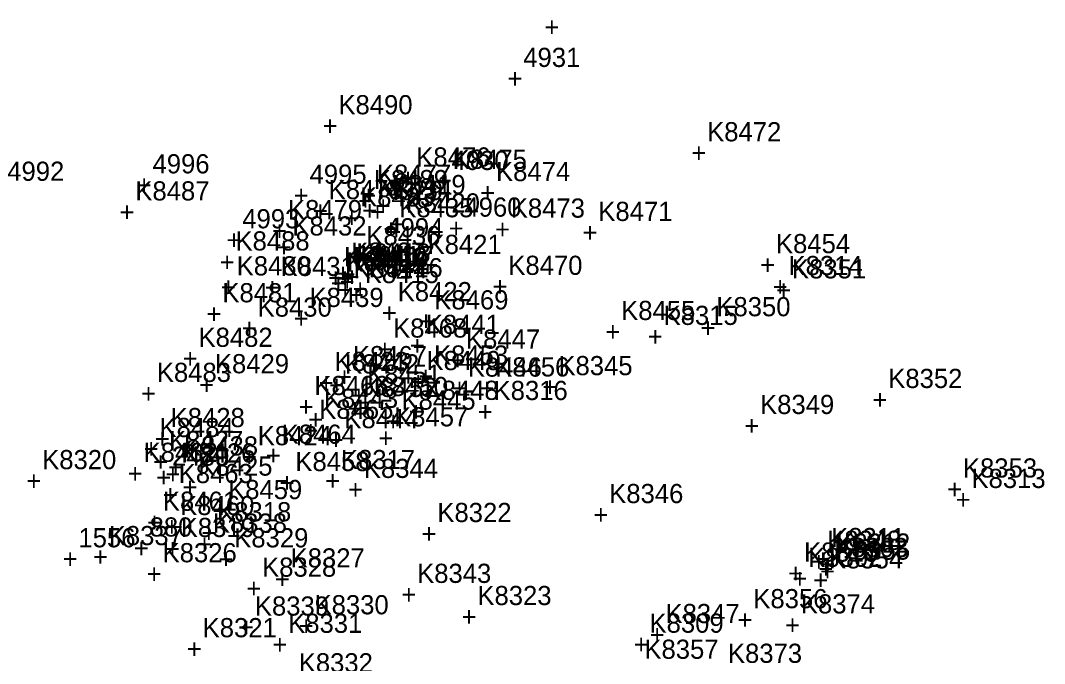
# Model space of a CAD drawing. Extents: x 1036751 to 1042192, y 772604 to 785439.
# Drawn here: x 1038800.5 to 1038934, y 778110.9 to 778194.7 of the extents above; entities that cross this region are included whole.
import ezdxf

# ---------------------------------------------------------------- set-up
doc = ezdxf.new("R2010")
doc.units = 0
for name, color, linetype in [('S_Control_Temp_Traverse', 7, 'Continuous'), ('S_Curb_Type_3', 7, 'Continuous'), ('S_Drainage_Culvert_Top', 7, 'Continuous'), ('S_Drainage_Ditch_Line', 7, 'Continuous'), ('S_Drainage_Invert', 7, 'Continuous'), ('S_Drainage_RipRap', 7, 'Continuous'), ('S_Ground_Elevation', 7, 'Continuous'), ('S_Ground_LevelString', 7, 'Continuous'), ('S_Misc_MiscItems', 7, 'Continuous'), ('S_Property_Garden', 7, 'Continuous'), ('S_Roadway_Drive_Paved', 7, 'Continuous'), ('S_Roadway_Edge_Pavement', 7, 'Continuous'), ('S_Roadway_Painted_Lines', 7, 'Continuous'), ('S_Traffic_JunctionBox', 7, 'Continuous'), ('S_Traffic_Sign_Base', 7, 'Continuous'), ('S_Traffic_Sign_SinglePost', 7, 'Continuous'), ('S_Trees_TreeLine', 7, 'Continuous')]:
    doc.layers.add(name, color=color, linetype=linetype)

msp = doc.modelspace()

# ---------------------------------------------------------------- texts
at = {"layer": 'S_Control_Temp_Traverse'}
for s, p in [('880', (1038817.35, 778127.4)), ('880', (1038817.35, 778127.4)), ('+', (1038815.29, 778124.65)), ('+', (1038815.29, 778124.65))]:
    msp.add_text(s, height=2.5, dxfattribs=at).set_placement(p)
at = {"layer": 'S_Curb_Type_3'}
for s, p in [('K8303', (1038906.58, 778124.72)), ('K8302', (1038903.21, 778123.45)), ('+', (1038904.52, 778121.97)), ('+', (1038901.14, 778120.7))]:
    msp.add_text(s, height=2.5, dxfattribs=at).set_placement(p)
at = {"layer": 'S_Drainage_Culvert_Top'}
for s, p in [('K8411', (1038844.18, 778162.13)), ('+', (1038842.12, 778159.38)), ('2479', (1038820.26, 778136.62)), ('+', (1038818.2, 778133.87))]:
    msp.add_text(s, height=2.5, dxfattribs=at).set_placement(p)
at = {"layer": 'S_Drainage_Ditch_Line'}
for s, p in [('K8440', (1038842.69, 778162.63)), ('+', (1038840.63, 778159.88)), ('K8439', (1038838.19, 778157.32)), ('+', (1038836.13, 778154.57)), ('K8438', (1038821.82, 778137.96)), ('+', (1038819.76, 778135.21))]:
    msp.add_text(s, height=2.5, dxfattribs=at).set_placement(p)
at = {"layer": 'S_Drainage_Invert'}
for s, p in [('K8410', (1038843.93, 778162.53)), ('+', (1038841.87, 778159.78)), ('2480', (1038820.29, 778136.64)), ('+', (1038818.23, 778133.89))]:
    msp.add_text(s, height=2.5, dxfattribs=at).set_placement(p)
at = {"layer": 'S_Drainage_RipRap'}
for s, p in [('K8419', (1038848.88, 778172.02)), ('K8433', (1038844.79, 778170.42)), ('K8434', (1038847.12, 778171.41)), ('K8420', (1038850.74, 778169.63)), ('+', (1038845.06, 778168.66)), ('+', (1038846.82, 778169.27)), ('K8432', (1038835.96, 778166.63)), ('+', (1038842.73, 778167.67)), ('+', (1038848.68, 778166.88)), ('K8421', (1038853.58, 778164.23)), ('+', (1038833.9, 778163.88)), ('K8431', (1038834.43, 778161.36)), ('+', (1038851.51, 778161.48)), ('+', (1038832.36, 778158.61)), ('K8422', (1038849.69, 778158.07)), ('K8430', (1038831.43, 778156.06)), ('+', (1038847.63, 778155.32)), ('+', (1038829.37, 778153.31)), ('K8429', (1038825.86, 778148.68)), ('K8423', (1038841.46, 778148.97)), ('+', (1038823.8, 778145.93)), ('+', (1038839.39, 778146.22)), ('K8428', (1038820.09, 778141.66)), ('+', (1038818.03, 778138.91)), ('K8427', (1038819.88, 778138.66)), ('K8424', (1038831.44, 778139.3)), ('K8426', (1038821.47, 778137.05)), ('+', (1038829.38, 778136.55)), ('+', (1038817.82, 778135.91)), ('K8425', (1038823.7, 778135.34)), ('+', (1038819.41, 778134.3)), ('+', (1038821.64, 778132.59))]:
    msp.add_text(s, height=2.5, dxfattribs=at).set_placement(p)
at = {"layer": 'S_Ground_Elevation'}
for s, p in [('+', (1038868.8, 778192.56)), ('4931', (1038866.06, 778188.6)), ('+', (1038864, 778185.85)), ('K8472', (1038890.03, 778178.91)), ('+', (1038887.97, 778176.16)), ('4996', (1038817.73, 778174.73)), ('K8476', (1038852.11, 778175.62)), ('4930', (1038856.71, 778175.17)), ('K8475', (1038856.86, 778175.32)), ('4992', (1038798.79, 778173.76)), ('4995', (1038838.2, 778173.38)), ('K8477', (1038846.99, 778173.38)), ('K8474', (1038862.51, 778173.72)), ('+', (1038850.05, 778172.87)), ('+', (1038854.65, 778172.42)), ('+', (1038854.8, 778172.57)), ('+', (1038815.67, 778171.98)), ('K8478', (1038840.69, 778171.37)), ('4929', (1038848.16, 778171.25)), ('+', (1038860.45, 778170.97)), ('+', (1038836.14, 778170.63)), ('+', (1038844.93, 778170.63)), ('4960', (1038858.39, 778169.09)), ('K8479', (1038835.38, 778168.76)), ('+', (1038838.63, 778168.62)), ('+', (1038846.09, 778168.5)), ('K8435', (1038849.9, 778169.01)), ('K8473', (1038864.43, 778168.96)), ('K8471', (1038875.84, 778168.53)), ('4993', (1038829.43, 778167.57)), ('4994', (1038848.21, 778166.4)), ('+', (1038833.31, 778166.01)), ('K8436', (1038845.6, 778165.37)), ('+', (1038847.83, 778166.26)), ('+', (1038856.33, 778166.34)), ('+', (1038862.37, 778166.21)), ('+', (1038873.78, 778165.78)), ('+', (1038827.37, 778164.82)), ('K8454', (1038899, 778164.33)), ('K8437', (1038843.64, 778163.22)), ('K8412', (1038843.9, 778162.62)), ('K8418', (1038844.3, 778163.1)), ('K8417', (1038844.82, 778162.76)), ('+', (1038846.14, 778163.65)), ('K8480', (1038828.7, 778161.43)), ('K8413', (1038843.04, 778161.94)), ('+', (1038843.54, 778162.62)), ('K8414', (1038843.93, 778161.07)), ('K8416', (1038845.89, 778161.19)), ('K8470', (1038864.11, 778161.5)), ('+', (1038896.94, 778161.58)), ('+', (1038841.58, 778160.47)), ('+', (1038842.24, 778160.35)), ('K8415', (1038845.4, 778160.43)), ('+', (1038840.98, 778159.19)), ('+', (1038841.84, 778159.87)), ('+', (1038842.76, 778160.01)), ('+', (1038826.64, 778158.68)), ('K8481', (1038826.83, 778157.93)), ('+', (1038841.87, 778158.32)), ('+', (1038843.33, 778157.68)), ('+', (1038843.83, 778158.44)), ('+', (1038862.05, 778158.75)), ('K8469', (1038854.46, 778157)), ('+', (1038824.77, 778155.18)), ('K8455', (1038878.82, 778155.62)), ('K8468', (1038849.09, 778153.33)), ('+', (1038852.4, 778154.25)), ('K8482', (1038823.72, 778152.12)), ('+', (1038876.76, 778152.87)), ('K8467', (1038843.84, 778149.73)), ('+', (1038847.03, 778150.58)), ('+', (1038821.66, 778149.37)), ('K8456', (1038862.4, 778148.26)), ('K8483', (1038818.29, 778147.55)), ('+', (1038841.78, 778146.98)), ('K8466', (1038838.83, 778145.84)), ('+', (1038860.34, 778145.51)), ('+', (1038816.23, 778144.8)), ('+', (1038836.77, 778143.09)), ('K8465', (1038839.46, 778142.74)), ('K8457', (1038849.22, 778141.76)), ('K8484', (1038818.64, 778140.37)), ('K8464', (1038834.56, 778139.49)), ('+', (1038837.4, 778139.99)), ('+', (1038847.16, 778139.01)), ('+', (1038816.58, 778137.62)), ('K8462', (1038816.56, 778137.13)), ('+', (1038832.5, 778136.74)), ('K8458', (1038836.35, 778135.93)), ('K8463', (1038821.14, 778134.37)), ('+', (1038814.5, 778134.38)), ('K8459', (1038827.58, 778132.28)), ('+', (1038834.29, 778133.18)), ('+', (1038819.08, 778131.62)), ('K8460', (1038821.33, 778130.2)), ('+', (1038825.52, 778129.53)), ('+', (1038819.27, 778127.45)), ('K8355', (1038906.81, 778124.39)), ('+', (1038904.75, 778121.64)), ('K8356', (1038896.05, 778118.06)), ('K8374', (1038902.25, 778117.38)), ('+', (1038893.99, 778115.32)), ('+', (1038900.19, 778114.63)), ('K8357', (1038881.85, 778111.47)), ('K8373', (1038892.74, 778110.94))]:
    msp.add_text(s, height=2.5, dxfattribs=at).set_placement(p)
at = {"layer": 'S_Ground_LevelString'}
for s, p in [('K8351', (1038901.09, 778161.04)), ('+', (1038899.03, 778158.29)), ('K8350', (1038891.23, 778156.11)), ('+', (1038889.17, 778153.36)), ('K8345', (1038870.64, 778148.43)), ('K8352', (1038913.64, 778146.76)), ('+', (1038868.57, 778145.68)), ('K8349', (1038896.93, 778143.37)), ('+', (1038911.58, 778144.01)), ('+', (1038894.87, 778140.62)), ('K8344', (1038845.28, 778135.04)), ('K8353', (1038923.38, 778135.09)), ('+', (1038843.22, 778132.29)), ('K8346', (1038877.26, 778131.76)), ('+', (1038921.32, 778132.34)), ('K8338', (1038825.59, 778127.91)), ('+', (1038875.2, 778129.01)), ('K8337', (1038812.02, 778126.28)), ('K8348', (1038905.68, 778125.67)), ('+', (1038823.53, 778125.16)), ('+', (1038809.96, 778123.53)), ('+', (1038903.62, 778122.92)), ('K8343', (1038852.22, 778121.36)), ('K8339', (1038831.07, 778117.1)), ('+', (1038850.16, 778118.61)), ('K8347', (1038884.6, 778116.12)), ('+', (1038829.01, 778114.35)), ('+', (1038882.54, 778113.37))]:
    msp.add_text(s, height=2.5, dxfattribs=at).set_placement(p)
at = {"layer": 'S_Misc_MiscItems'}
for s, p in [('K8453', (1038854.43, 778149.81)), ('+', (1038852.37, 778147.06)), ('K8452', (1038845.21, 778145.59)), ('+', (1038843.15, 778142.84))]:
    msp.add_text(s, height=2.5, dxfattribs=at).set_placement(p)
at = {"layer": 'S_Property_Garden'}
for s, p in [('K8441', (1038853.34, 778153.8)), ('K8447', (1038858.59, 778151.89)), ('+', (1038851.28, 778151.05)), ('K8442', (1038842.82, 778148.65)), ('+', (1038856.53, 778149.14)), ('K8446', (1038858.83, 778148.24)), ('+', (1038840.76, 778145.9)), ('+', (1038856.77, 778145.49)), ('K8443', (1038840.08, 778144.17)), ('K8445', (1038850.18, 778143.94)), ('K8444', (1038842.73, 778141.52)), ('+', (1038838.02, 778141.42)), ('+', (1038848.12, 778141.19)), ('+', (1038840.67, 778138.77))]:
    msp.add_text(s, height=2.5, dxfattribs=at).set_placement(p)
at = {"layer": 'S_Roadway_Drive_Paved'}
for s, p in [('K8314', (1038900.64, 778161.47)), ('+', (1038898.58, 778158.72)), ('K8315', (1038884.35, 778154.98)), ('+', (1038882.29, 778152.23)), ('K8316', (1038862.19, 778145.19)), ('+', (1038860.13, 778142.44)), ('K8320', (1038803.34, 778136.18)), ('K8317', (1038842.29, 778136.19)), ('+', (1038840.23, 778133.44)), ('K8313', (1038924.49, 778133.73)), ('+', (1038801.28, 778133.43)), ('+', (1038922.43, 778130.98)), ('K8318', (1038826.15, 778129.39)), ('K8319', (1038821.41, 778127.34)), ('+', (1038824.09, 778126.64)), ('K8311', (1038906.19, 778126.02)), ('K8312', (1038906.84, 778125.31)), ('+', (1038819.35, 778124.59)), ('K8310', (1038902.66, 778124.13)), ('+', (1038904.13, 778123.27)), ('+', (1038904.77, 778122.56)), ('+', (1038900.6, 778121.38)), ('K8309', (1038882.52, 778114.87)), ('+', (1038880.46, 778112.12))]:
    msp.add_text(s, height=2.5, dxfattribs=at).set_placement(p)
at = {"layer": 'S_Roadway_Edge_Pavement'}
for s, p in [('1556', (1038808.07, 778126)), ('+', (1038806.01, 778123.25))]:
    msp.add_text(s, height=2.5, dxfattribs=at).set_placement(p)
at = {"layer": 'S_Roadway_Painted_Lines'}
for s, p in [('K8322', (1038854.86, 778129.29)), ('K8329', (1038828.38, 778125.99)), ('+', (1038852.8, 778126.54)), ('K8326', (1038819.04, 778124.05)), ('+', (1038826.32, 778123.24)), ('K8327', (1038835.73, 778123.37)), ('K8328', (1038832.01, 778122.17)), ('+', (1038816.97, 778121.3)), ('+', (1038833.67, 778120.62)), ('+', (1038829.95, 778119.42)), ('K8323', (1038860.08, 778118.47)), ('K8330', (1038838.85, 778117.27)), ('K8331', (1038835.41, 778114.85)), ('+', (1038858.02, 778115.72)), ('K8321', (1038824.26, 778114.28)), ('+', (1038836.79, 778114.52)), ('+', (1038833.34, 778112.1)), ('+', (1038822.2, 778111.53)), ('K8332', (1038836.79, 778109.7))]:
    msp.add_text(s, height=2.5, dxfattribs=at).set_placement(p)
at = {"layer": 'S_Traffic_JunctionBox'}
for s, p in [('K8448', (1038853.19, 778145.21)), ('+', (1038851.12, 778142.46)), ('K8354', (1038905.92, 778123.25)), ('+', (1038903.86, 778120.5))]:
    msp.add_text(s, height=2.5, dxfattribs=at).set_placement(p)
at = {"layer": 'S_Traffic_Sign_Base'}
for s, p in [('K8449', (1038853.45, 778149.09)), ('K8451', (1038845.7, 778147.32)), ('K8450', (1038846.58, 778145.7)), ('+', (1038851.39, 778146.34)), ('+', (1038843.64, 778144.57)), ('+', (1038844.52, 778142.95))]:
    msp.add_text(s, height=2.5, dxfattribs=at).set_placement(p)
at = {"layer": 'S_Traffic_Sign_SinglePost'}
for s, p in [('K8461', (1038819.08, 778130.76)), ('+', (1038817.02, 778128.01))]:
    msp.add_text(s, height=2.5, dxfattribs=at).set_placement(p)
at = {"layer": 'S_Trees_TreeLine'}
for s, p in [('K8490', (1038841.96, 778182.43)), ('+', (1038839.9, 778179.68)), ('K8489', (1038846.58, 778172.68)), ('K8487', (1038815.49, 778171.2)), ('+', (1038844.52, 778169.93)), ('+', (1038813.42, 778168.45)), ('K8488', (1038828.54, 778164.68)), ('+', (1038826.48, 778161.93))]:
    msp.add_text(s, height=2.5, dxfattribs=at).set_placement(p)

doc.saveas('drawing.dxf')
